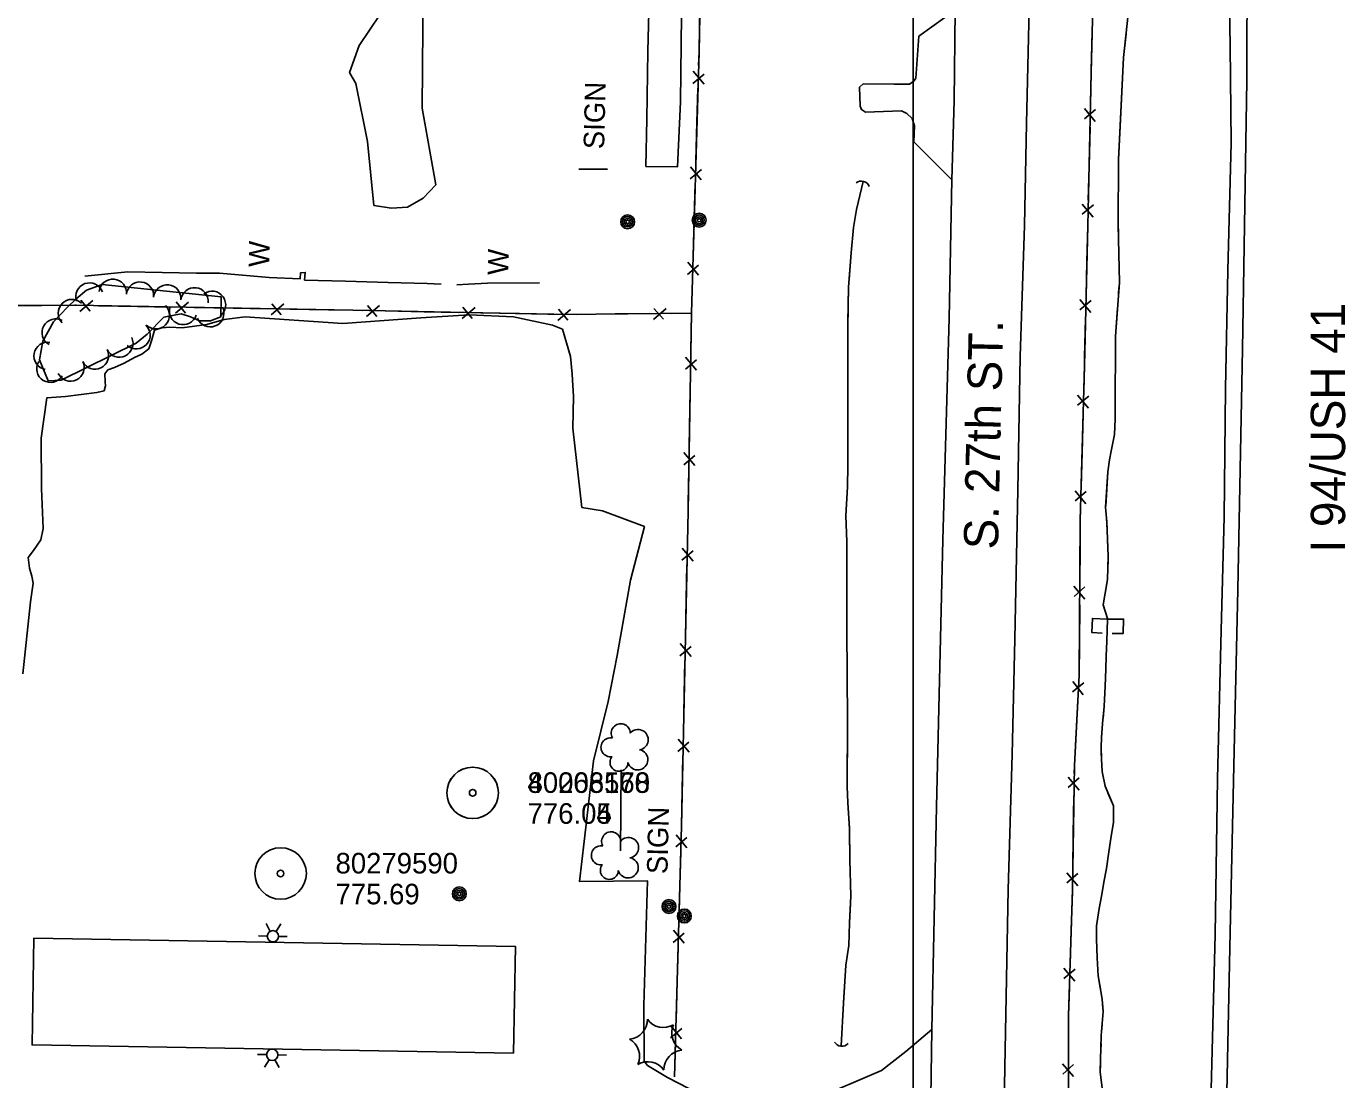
# Model space of a CAD drawing. Extents: x 591954 to 597000, y 198576 to 213500.
# Drawn here: x 593741.5 to 594126.1, y 209562.4 to 209869.5 of the extents above; entities that cross this region are included whole.
import ezdxf

# ---------------------------------------------------------------- set-up
doc = ezdxf.new("R2010")
doc.units = 0
for name, color, linetype in [('1', 7, 'Continuous'), ('Level 10', 7, 'Continuous'), ('Level 11', 7, 'Continuous'), ('Level 12', 7, 'Continuous'), ('Level 14', 7, 'Continuous'), ('Level 15', 7, 'Continuous'), ('Level 17', 7, 'Continuous'), ('Level 18', 7, 'Continuous'), ('Level 19', 7, 'Continuous'), ('Level 6', 7, 'Continuous')]:
    doc.layers.add(name, color=color, linetype=linetype)

msp = doc.modelspace()

# ---------------------------------------------------------------- linework, layer by layer
at = {"layer": 'Level 10'}
for p, q in [((594000, 209500), (594000, 210500)), ((594000, 208500), (594000, 210000))]:
    msp.add_line(p, q, dxfattribs=at)
at = {"layer": 'Level 11'}
for points in [[(594091.31, 209554.07), (594092.34, 209600.93), (594093.45, 209653.95), (594094.63, 209705.34), (594096.03, 209775.4), (594097.26, 209853.63), (594097.48, 209924.76), (594097.61, 209991.03), (594097.47, 210057.15), (594095.7, 210107.83), (594092.7, 210159.9), (594089.31, 210197.02), (594083.96, 210243.66), (594078.7, 210282.56), (594060.94, 210385.67)], [(594086.72, 209555.89), (594087.98, 209604.77), (594088.71, 209650.16), (594089.73, 209693.47), (594090.69, 209726.46), (594091.06, 209763.95), (594091.76, 209798.33), (594092.66, 209835.57), (594092.35, 209863.88), (594091.82, 209896.8)], [(594034.04, 209883.08), (594033, 209841.22), (594032.48, 209811.52), (594031.17, 209773.23), (594030.5, 209734.28), (594029.58, 209690.89), (594028.84, 209657.2), (594027.72, 209617.9), (594026.37, 209550.34)], [(594011.28, 209824.83), (594011.94, 209847.85), (594012.22, 209874.26)], [(594005.47, 209577.06), (594006.8, 209641.94), (594008.65, 209719.87), (594010.5, 209784.41), (594011.28, 209824.83)], [(594005.08, 209550.72), (594005.47, 209577.06)]]:
    msp.add_lwpolyline(points, dxfattribs=at)
at = {"layer": 'Level 12'}
msp.add_lwpolyline([(593883.47, 209570.18), (593743.1, 209572.58), (593743.64, 209603.71), (593884.01, 209601.3), (593883.47, 209570.18)], dxfattribs=at)
at = {"layer": 'Level 14'}
for p, q in [((593812.54, 209605.67), (593811.34, 209607.97)), ((593814.24, 209605.66), (593815.61, 209607.89)), ((593811.7, 209604.3), (593809.1, 209604.37)), ((593814.98, 209604.21), (593817.5, 209604.14)), ((593812.46, 209602.81), (593812.29, 209602.53)), ((593814.1, 209602.77), (593814.25, 209602.5)), ((593811.48, 209569.73), (593808.88, 209569.8)), ((593812.32, 209571.1), (593812.16, 209571.4)), ((593814.02, 209571.09), (593814.19, 209571.37)), ((593814.76, 209569.64), (593817.28, 209569.57)), ((593812.24, 209568.24), (593810.88, 209566.05)), ((593813.88, 209568.2), (593815.12, 209566.02))]:
    msp.add_line(p, q, dxfattribs=at)
for points in [[(593910.85, 209827.88), (593902.52, 209827.87)], [(593914.65, 209629.17), (593914.81, 209652.75)]]:
    msp.add_lwpolyline(points, dxfattribs=at)
for centre, radius in [((593937.58, 209813.02), 2.02), ((593916.74, 209812.56), 2.02), ((593916.74, 209812.58), 1.52), ((593916.75, 209812.54), 1.01), ((593916.75, 209812.55), 0.502), ((593937.58, 209813.03), 1.52), ((593937.58, 209812.99), 1.01), ((593937.59, 209813), 0.502), ((593867.67, 209616.61), 2.02), ((593867.67, 209616.62), 1.52), ((593867.68, 209616.58), 1.01), ((593867.68, 209616.59), 0.502), ((593928.8, 209612.91), 2.02), ((593928.79, 209612.92), 1.52), ((593928.8, 209612.88), 1.01), ((593928.8, 209612.89), 0.502), ((593933.27, 209610.14), 2.02), ((593933.27, 209610.15), 1.52), ((593933.28, 209610.11), 1.01), ((593933.28, 209610.12), 0.502), ((593813.34, 209604.24), 1.64), ((593813.12, 209569.67), 1.64)]:
    msp.add_circle(centre, radius, dxfattribs=at)
at = {"layer": 'Level 15'}
for p, q in [((593935.79, 209852.91), (593939.04, 209855.61)), ((593939.02, 209852.65), (593935.89, 209856.46)), ((594049.92, 209845.56), (594053.07, 209841.77)), ((594053.16, 209845.32), (594049.92, 209842.6)), ((593934.98, 209825.06), (593938.23, 209827.77)), ((593938.21, 209824.8), (593935.08, 209828.61)), ((594049.27, 209817.71), (594052.43, 209813.92)), ((594052.51, 209817.47), (594049.27, 209814.74)), ((593934.17, 209797.21), (593937.42, 209799.92)), ((593937.4, 209796.95), (593934.27, 209800.76)), ((593757.07, 209786.44), (593760.85, 209789.61)), ((593757.3, 209789.67), (593760.04, 209786.45)), ((593784.93, 209785.94), (593788.7, 209789.11)), ((593785.16, 209789.18), (593787.89, 209785.96)), ((593812.78, 209785.44), (593816.56, 209788.61)), ((593813.01, 209788.68), (593815.75, 209785.46)), ((593840.64, 209784.94), (593844.42, 209788.1)), ((593840.87, 209788.17), (593843.6, 209784.95)), ((594048.62, 209789.86), (594051.77, 209786.07)), ((594051.86, 209789.61), (594048.62, 209786.89)), ((593868.49, 209784.38), (593872.27, 209787.55)), ((593868.72, 209787.62), (593871.46, 209784.39)), ((593896.37, 209783.8), (593900.1, 209787.02)), ((593896.56, 209787.05), (593899.33, 209783.85)), ((593924.25, 209784.04), (593927.94, 209787.32)), ((593924.39, 209787.28), (593927.22, 209784.14)), ((593936.8, 209769.34), (593933.63, 209773.11)), ((593933.57, 209769.57), (593936.78, 209772.31)), ((594051.18, 209761.76), (594047.93, 209759.05)), ((594047.94, 209762.01), (594051.08, 209758.21)), ((593933.1, 209741.71), (593936.32, 209744.45)), ((593936.33, 209741.49), (593933.16, 209745.26)), ((594050.43, 209733.91), (594047.19, 209731.2)), ((594047.2, 209734.16), (594050.34, 209730.36)), ((593932.57, 209713.86), (593935.8, 209716.59)), ((593935.81, 209713.63), (593932.65, 209717.41)), ((594046.84, 209706.27), (594050.05, 209702.53)), ((594050.07, 209706.08), (594046.88, 209703.31)), ((593931.99, 209686.01), (593935.22, 209688.74)), ((593935.22, 209685.77), (593932.06, 209689.56)), ((594049.78, 209678.15), (594046.46, 209675.53)), ((594046.56, 209678.5), (594049.59, 209674.61)), ((593934.64, 209657.92), (593931.48, 209661.7)), ((593931.4, 209658.16), (593934.63, 209660.88)), ((594045.18, 209650.61), (594048.36, 209646.84)), ((594048.42, 209650.39), (594045.2, 209647.64)), ((593930.78, 209630.31), (593934.03, 209633.02)), ((593934.02, 209630.05), (593930.88, 209633.86)), ((594044.76, 209622.75), (594047.95, 209618.98)), ((594048, 209622.53), (594044.79, 209619.78)), ((593930.02, 209602.46), (593933.27, 209605.17)), ((593933.26, 209602.2), (593930.12, 209606.01)), ((594047.18, 209594.66), (594043.92, 209591.96)), ((594043.95, 209594.93), (594047.07, 209591.11)), ((593929.26, 209574.61), (593932.51, 209577.32)), ((593932.49, 209574.36), (593929.36, 209578.16)), ((594043.52, 209567.02), (594046.77, 209563.31)), ((594046.76, 209566.85), (594043.59, 209564.06))]:
    msp.add_line(p, q, dxfattribs=at)
for points in [[(593959.51, 210454.78), (593974.64, 210411.96), (593987.13, 210374.2), (593999.11, 210340.41), (594023.86, 210270.06), (594042.85, 210215.9), (594047.69, 210154.51), (594052.6, 210098.45), (594056.62, 210050.32), (594056.88, 210021.22), (594055.97, 209983.92), (594054.43, 209941.9), (594052.89, 209894.6), (594051.91, 209856.12), (594050.87, 209811.42), (594049.91, 209770.63), (594048.71, 209725.59), (594048.4, 209680.32), (594046.97, 209654.07), (594046.43, 209617.89), (594045.25, 209581.13), (594045.27, 209558.54), (594045.21, 209556.37)], [(593935.34, 209785.89), (593937.56, 209862.11), (593939.67, 209972.11), (593940.13, 210009.6)], [(593937.7, 209869.43), (593937.89, 209879.39)], [(593937.44, 209858.12), (593937.56, 209862.11), (593937.7, 209869.43)], [(594052.21, 209867.96), (594051.92, 209856.64)], [(594051.92, 209856.64), (594051.91, 209856.12), (594051.69, 209846.68)], [(593936.96, 209841.58), (593937.25, 209851.54)], [(593936.63, 209830.27), (593936.96, 209841.58)], [(594051.54, 209840.1), (594051.27, 209828.79)], [(594051.27, 209828.79), (594051.04, 209818.83)], [(593936.15, 209813.74), (593936.44, 209823.69)], [(593935.82, 209802.42), (593936.15, 209813.74)], [(594050.89, 209812.25), (594050.87, 209811.42), (594050.62, 209800.93)], [(594050.62, 209800.93), (594050.39, 209790.98)], [(593862.41, 209794.4), (593858.34, 209794.58), (593846.96, 209794.84), (593834.51, 209795.28), (593822.57, 209795.56), (593822.77, 209797.77), (593821.41, 209797.72), (593821.24, 209795.92), (593812.2, 209796.34), (593797.74, 209797.62), (593791.02, 209797.57), (593771.07, 209797.98), (593758.49, 209796.74)], [(593935.34, 209785.89), (593935.63, 209795.84)], [(593891.07, 209794.77), (593875.86, 209794.68), (593870.36, 209794.39), (593866.92, 209794.22)], [(593677.4, 209540.09), (593681.55, 209631.44), (593686.02, 209748.26), (593687.78, 209788.12), (593755.63, 209788.2), (593836.66, 209786.76), (593898.23, 209785.53), (593935.34, 209785.89)], [(593734.67, 209788.18), (593745.99, 209788.19)], [(593745.99, 209788.19), (593755.63, 209788.2), (593755.94, 209788.2)], [(593762.52, 209788.08), (593773.84, 209787.88)], [(593773.84, 209787.88), (593783.8, 209787.7)], [(593790.38, 209787.58), (593801.7, 209787.38)], [(593801.7, 209787.38), (593811.65, 209787.2)], [(593818.23, 209787.08), (593829.56, 209786.88)], [(593829.56, 209786.88), (593836.66, 209786.76), (593839.51, 209786.7)], [(593846.09, 209786.57), (593857.41, 209786.34)], [(593857.41, 209786.34), (593867.36, 209786.14)], [(593873.95, 209786.01), (593885.26, 209785.79)], [(593885.26, 209785.79), (593895.22, 209785.59)], [(593901.8, 209785.56), (593913.12, 209785.67)], [(593913.12, 209785.67), (593923.08, 209785.77)], [(593929.66, 209785.83), (593935.34, 209785.89)], [(593930.45, 209563.29), (593932.45, 209636.37), (593934.37, 209728.16), (593935.34, 209785.89)], [(593935.16, 209774.79), (593935.34, 209785.89)], [(594050.23, 209784.4), (594049.97, 209773.08)], [(594049.97, 209773.08), (594049.91, 209770.63), (594049.71, 209763.13)], [(593934.88, 209758.26), (593935.04, 209768.21)], [(593934.69, 209746.94), (593934.88, 209758.26)], [(594049.54, 209756.55), (594049.23, 209745.23)], [(594049.23, 209745.23), (594048.97, 209735.28)], [(593934.41, 209730.4), (593934.58, 209740.36)], [(593934.18, 209719.08), (593934.37, 209728.16), (593934.41, 209730.4)], [(594048.79, 209728.7), (594048.71, 209725.59), (594048.65, 209717.38)], [(594048.65, 209717.38), (594048.58, 209707.42)], [(593933.83, 209702.55), (593934.04, 209712.5)], [(593933.6, 209691.23), (593933.83, 209702.55)], [(594048.54, 209700.84), (594048.46, 209689.52)], [(594058.03, 209692.48), (594061.22, 209692.56), (594061.35, 209696.74), (594056.66, 209696.73), (594052.26, 209696.91), (594052.06, 209692.84), (594055.06, 209692.61)], [(594048.46, 209689.52), (594048.4, 209680.32), (594048.35, 209679.56)], [(593933.25, 209674.69), (593933.46, 209684.65)], [(593933.01, 209663.38), (593933.25, 209674.69)], [(594048, 209672.99), (594047.39, 209661.69)], [(594047.39, 209661.69), (594046.97, 209654.07), (594046.94, 209651.74)], [(593932.67, 209646.84), (593932.88, 209656.79)], [(593932.43, 209635.52), (593932.45, 209636.37), (593932.67, 209646.84)], [(594046.84, 209645.16), (594046.67, 209633.84)], [(594046.67, 209633.84), (594046.52, 209623.88)], [(593931.97, 209618.99), (593932.24, 209628.94)], [(593931.67, 209607.67), (593931.97, 209618.99)], [(594046.41, 209617.3), (594046.05, 209605.99)], [(594046.05, 209605.99), (594045.73, 209596.04)], [(593931.21, 209591.14), (593931.48, 209601.09)], [(593930.9, 209579.82), (593931.21, 209591.14)], [(594045.52, 209589.46), (594045.25, 209581.13), (594045.25, 209578.14)], [(594045.25, 209578.14), (594045.26, 209568.18)], [(593930.45, 209563.29), (593930.72, 209573.24)]]:
    msp.add_lwpolyline(points, dxfattribs=at)
for centre, start, end in [((593984.89, 209821.91), 22.3381, 128.5777), ((593979.19, 209574.67), 210.7721, 317.0116)]:
    msp.add_arc(centre, 2.5, start, end, dxfattribs=at)
at = {"layer": 'Level 17'}
for points in [[(593817.2, 209957.57), (593831.95, 209961.46), (593837.63, 209961.64), (593840.77, 209960.49), (593842.74, 209958.25), (593844.01, 209947.49), (593844.5, 209878.07), (593844.47, 209872.94), (593838.47, 209863.97), (593835.68, 209856.08), (593837.51, 209852.91), (593840.95, 209835.99), (593842.79, 209817.33), (593847.87, 209816.55), (593852.52, 209816.86), (593857.15, 209819.42), (593860.79, 209823.33), (593856.81, 209845.73), (593857.38, 209916.41), (593857.82, 209957.12), (593859.55, 209969.52), (593862.11, 209978.24), (593875.52, 209996.25)], [(593932.42, 209970.11), (593933.31, 209953.24), (593932.36, 209914.25), (593932.52, 209881.21), (593932.11, 209847.5), (593931.28, 209828.54), (593922.06, 209828.72), (593922.34, 209842.48), (593922.66, 209862.28), (593922.9, 209873.68), (593923.6, 209898.68), (593924.46, 209916.94), (593924.74, 209923.21), (593924.41, 209943.26), (593923.77, 209956.53), (593923.75, 209970.8)], [(594010.25, 209872.85), (594009.25, 209872.13), (594001.59, 209866.64), (594000.74, 209854.47), (594000.13, 209853.6), (593998.87, 209852.7), (593997.7, 209852.64), (593994.43, 209852.71), (593985.38, 209852.74), (593984.31, 209851.8), (593984.53, 209846.26), (593984.95, 209845.25), (593986.06, 209844.51), (593996.59, 209844.89), (593998.16, 209844.17), (593999.68, 209842.66), (594000.35, 209840.49), (594000.2, 209835.82), (594011.28, 209824.83)], [(593921.55, 209567.84), (593921.46, 209584.03), (593922.49, 209620.43), (593902.67, 209620.21), (593904.06, 209631.85), (593906.79, 209655.41), (593911.04, 209672.65), (593913.65, 209686.12), (593917.57, 209708.11), (593921.62, 209723.71), (593909.4, 209728.29), (593903.38, 209729.26), (593900.81, 209752.42), (593900.92, 209761.62), (593900.55, 209768.13), (593900.12, 209773.24), (593897.72, 209781.2), (593894.87, 209782.37), (593883.45, 209784.89), (593870.59, 209785.43), (593856.45, 209784.6), (593833.71, 209782.89), (593805.2, 209784.82), (593799.12, 209784.05), (593794.1, 209782.64), (593786.87, 209781.68), (593783.32, 209781.79), (593780.94, 209781.68), (593778.79, 209780.96), (593777.91, 209777.84), (593777.14, 209775.52), (593775.07, 209773.97), (593772.97, 209772.98), (593769.97, 209771.34), (593767.18, 209770.08), (593765.25, 209769.43), (593764.33, 209768.22), (593764.4, 209765.89), (593764.5, 209764.73), (593764.11, 209763.31), (593761.98, 209762.83), (593752.85, 209761.64), (593747.41, 209761.19), (593745.74, 209749.49), (593745.89, 209734.8), (593746.32, 209723.1), (593745.69, 209719.81), (593743.51, 209716.67), (593742.02, 209714.63), (593742.41, 209711.53), (593743.08, 209709.23), (593743.41, 209707.19), (593742.65, 209701.79), (593740.45, 209680.73)], [(594005.47, 209577.06), (593997.81, 209570.62), (593990.8, 209565.1), (593971.23, 209556.73), (593957.64, 209556.9), (593940.71, 209557.81), (593934.54, 209559.89), (593928.32, 209563.04), (593922.55, 209566.54), (593921.55, 209567.84)]]:
    msp.add_lwpolyline(points, dxfattribs=at)
at = {"layer": 'Level 18'}
msp.add_lwpolyline([(593773.43, 209777.14), (593776.69, 209779.8), (593781.58, 209784.71), (593786.58, 209785.7), (593789.33, 209784.81), (593791.9, 209783.72), (593795.17, 209783.69), (593798.19, 209784.86), (593798.28, 209790.66), (593763.57, 209794.29), (593758.98, 209792.66), (593755.94, 209790.09), (593753.44, 209787.63), (593749.35, 209783.42), (593746.27, 209777.76), (593745.32, 209772.3), (593747.86, 209766.18), (593751.58, 209766.36), (593773.43, 209777.14)], dxfattribs=at)
for centre, radius, start, end in [((593914.75, 209663.42), 2.78, 1.3946, 209.1675), ((593911.75, 209659.34), 2.78, 78.0716, 279.0826), ((593919.79, 209661.56), 2.97, 278.4237, 139.6575), ((593919.68, 209655.7), 2.97, 196.0745, 79.0477), ((593914.21, 209654.94), 2.61, 140.7797, 358.7123), ((593911.94, 209631.92), 2.78, 1.3946, 209.1675), ((593908.94, 209627.84), 2.78, 78.0716, 279.0826), ((593916.98, 209630.06), 2.97, 278.4237, 139.6575), ((593916.87, 209624.21), 2.97, 196.0745, 79.0477), ((593911.4, 209623.44), 2.61, 140.7797, 358.7123), ((593916.78, 209579.96), 5.72, 275.2113, 0.9762), ((593927.18, 209583.36), 5.72, 215.2113, 300.9762), ((593935.32, 209576.05), 5.72, 155.2113, 240.9762), ((593914.52, 209569.26), 5.72, 335.2113, 60.9762), ((593933.06, 209565.35), 5.72, 95.2113, 180.9762), ((593922.66, 209561.95), 5.72, 35.2113, 120.9762)]:
    msp.add_arc(centre, radius, start, end, dxfattribs=at)
for centre, major_axis, ratio, start_param, end_param in [((593766.64, 209791.86), (2.86, 2.79), 0.996475, 5.40392, 8.545245), ((593759.85, 209790.76), (2.97, 2.67), 0.995849, 5.889612, 9.030937), ((593774.58, 209791.03), (2.86, 2.79), 0.996475, 5.40392, 8.545245), ((593782.52, 209790.2), (2.86, 2.79), 0.996475, 5.40392, 8.545245), ((593790.46, 209789.37), (2.86, 2.79), 0.996475, 5.40392, 8.545245), ((593795.58, 209788.34), (1.14, -3.83), 0.99657, 0.340366, 3.481692), ((593754.71, 209785.95), (2.04, 3.44), 0.994862, 6.045583, 9.186908), ((593779.22, 209785.29), (-2.74, -2.91), 0.995155, 6.253959, 9.395284), ((593750.01, 209780.27), (1.97, 3.48), 0.995255, 0.016088, 3.157413), ((593787.15, 209786.55), (-3.5, 1.94), 0.999352, 0.193403, 3.334729), ((593795.06, 209785.89), (-3.95, -0.63), 0.99614, 0.212479, 3.353804), ((593773.58, 209779.48), (-2.19, -3.35), 0.994996, 6.124495, 9.26582), ((593747.64, 209773.46), (0.19, 4), 0.996182, 6.158984, 9.30031), ((593768.59, 209777.08), (-0.97, -3.88), 0.990291, 5.410305, 8.551631), ((593761.46, 209773.56), (-0.97, -3.88), 0.990291, 5.410305, 8.551631), ((593748.48, 209769.7), (-1.84, 3.55), 0.99846, 0.54232, 3.683645), ((593754.33, 209770.04), (-0.97, -3.88), 0.990291, 5.410305, 8.551631)]:
    msp.add_ellipse(centre, major_axis=major_axis, ratio=ratio, start_param=start_param, end_param=end_param, dxfattribs=at)
at = {"layer": 'Level 19'}
for points in [[(594062.62, 209873.13), (594061.33, 209860.42), (594059.87, 209830.74), (594059.79, 209811.69), (594060.1, 209794.87), (594058.98, 209779.25), (594058.97, 209770.73), (594058.88, 209765.66), (594058.89, 209760.56), (594058.85, 209755.01), (594058.7, 209750.54), (594057.7, 209745.67), (594057.21, 209743.19), (594056.75, 209739.65), (594056.1, 209729.37), (594056.43, 209725.07), (594056.85, 209715.08), (594056.61, 209708.28), (594055.39, 209700.85), (594056.61, 209696.86)], [(594060.24, 209838.38), (594061.33, 209860.42), (594062.04, 209867.32)], [(594059.83, 209809.39), (594059.79, 209811.69), (594059.87, 209830.74), (594060.24, 209838.38)], [(593985.42, 209824.32), (593983.46, 209816.13), (593982.55, 209810.89), (593981.9, 209803.55), (593981.18, 209793.51), (593980.93, 209783.23), (593980.92, 209741.37), (593980.82, 209735.25), (593980.34, 209726.83), (593980.66, 209719.3), (593980.64, 209710.06), (593980.66, 209700.66), (593980.67, 209693.76), (593980.79, 209680.6), (593980.87, 209667.05), (593980.75, 209647.91), (593980.94, 209643.11), (593981.42, 209635.55), (593981.51, 209626.53), (593981.77, 209616.07), (593981.45, 209608.19), (593981.24, 209601.55), (593980.37, 209595.84), (593979.7, 209584.72), (593979, 209572.25)], [(593985.42, 209824.32), (593983.46, 209816.13), (593982.55, 209810.89), (593981.9, 209803.55), (593981.33, 209795.68)], [(594059.94, 209803.39), (594059.91, 209805.39)], [(594060.05, 209797.39), (594060.01, 209799.39)], [(594059.85, 209791.4), (594059.99, 209793.4)], [(593981.13, 209791.69), (593981.08, 209789.69)], [(593980.99, 209785.69), (593980.94, 209783.69)], [(594058.87, 209758.43), (594058.89, 209760.56), (594058.88, 209765.66), (594058.97, 209770.73), (594058.98, 209779.25), (594059.56, 209787.41)], [(593980.93, 209779.69), (593980.93, 209777.69)], [(593980.93, 209773.69), (593980.92, 209744.69)], [(594056.11, 209729.64), (594056.75, 209739.65), (594057.21, 209743.19), (594057.7, 209745.67), (594058.7, 209750.54), (594058.85, 209755.01), (594058.87, 209758.43)], [(593980.92, 209744.69), (593980.92, 209741.37), (593980.82, 209735.25), (593980.34, 209726.83), (593980.66, 209719.3), (593980.65, 209715.72)], [(594056.49, 209723.65), (594056.43, 209725.07), (594056.38, 209725.65)], [(594056.74, 209717.65), (594056.66, 209719.65)], [(593980.65, 209711.72), (593980.64, 209710.06), (593980.64, 209709.72)], [(594056.73, 209711.66), (594056.8, 209713.66)], [(594056.61, 209696.86), (594055.39, 209700.85), (594056.51, 209707.67)], [(593980.65, 209705.72), (593980.65, 209703.72)], [(593980.66, 209699.72), (593980.66, 209697.72)], [(594056.61, 209696.73), (594056.48, 209690.26), (594056.24, 209685.91), (594056.12, 209682.14), (594055.97, 209677.19), (594055.65, 209671.26), (594055.19, 209666.32), (594054.91, 209662.09), (594054.77, 209659.48), (594054.85, 209655.9), (594055.06, 209652.24), (594055.93, 209648.01), (594058.43, 209642.27), (594058.36, 209637.45), (594057.68, 209633.38), (594056.9, 209628.15), (594056.32, 209623.97), (594055.54, 209619.99), (594055.02, 209616.39), (594054.21, 209612.37), (594053.4, 209607.24), (594053.43, 209603.51), (594053.67, 209597.97), (594053.92, 209592.7), (594055.08, 209585.87), (594055.34, 209582.28), (594054.83, 209575.27), (594054.47, 209564.7), (594055.73, 209554.45)], [(594055.33, 209667.76), (594055.65, 209671.26), (594055.97, 209677.19), (594056.12, 209682.14), (594056.24, 209685.91), (594056.48, 209690.26), (594056.61, 209696.73)], [(594056.61, 209696.86), (594056.61, 209696.73)], [(594056.61, 209696.86), (594056.61, 209696.73)], [(593980.67, 209693.72), (593980.79, 209680.6), (593980.87, 209667.05), (593980.86, 209664.72)], [(593980.86, 209664.72), (593980.75, 209647.91), (593980.94, 209643.11), (593981.41, 209635.74)], [(594054.9, 209661.78), (594054.91, 209662.09), (594055.02, 209663.77)], [(594054.86, 209655.78), (594054.85, 209655.9), (594054.81, 209657.78)], [(594055.55, 209649.84), (594055.15, 209651.8)], [(594055.2, 209617.65), (594055.54, 209619.99), (594056.32, 209623.97), (594056.9, 209628.15), (594057.68, 209633.38), (594058.36, 209637.45), (594058.43, 209642.27), (594056.78, 209646.05)], [(593981.46, 209631.74), (593981.48, 209629.74)], [(593981.53, 209625.74), (593981.58, 209623.75)], [(593981.68, 209619.75), (593981.73, 209617.75)], [(594054.57, 209588.87), (594053.92, 209592.7), (594053.67, 209597.97), (594053.43, 209603.51), (594053.4, 209607.24), (594054.21, 209612.37), (594055.02, 209616.39), (594055.2, 209617.65)], [(593981.67, 209613.75), (593981.45, 209608.19), (593981.24, 209601.55), (593980.37, 209595.84), (593979.71, 209584.85)], [(593979.71, 209584.85), (593979.7, 209584.72), (593979, 209572.25)], [(594055.29, 209582.93), (594055.15, 209584.92)], [(594054.95, 209576.94), (594055.1, 209578.93)], [(594054.68, 209570.95), (594054.75, 209572.95)], [(594054.46, 209550.86), (594055.52, 209552.53), (594055.73, 209554.45), (594054.47, 209564.7), (594054.55, 209566.95)]]:
    msp.add_lwpolyline(points, dxfattribs=at)
at = {"layer": 'Level 6'}
for centre, radius in [((593871.56, 209646.04), 7.5), ((593871.56, 209646.04), 7.5), ((593871.57, 209646.04), 7.5), ((593871.57, 209646.04), 7.5), ((593871.56, 209646.04), 0.96), ((593871.56, 209646.04), 0.96), ((593871.57, 209646.04), 0.96), ((593871.57, 209646.04), 0.96), ((593815.58, 209622.55), 7.5), ((593815.58, 209622.55), 7.5), ((593815.58, 209622.55), 0.96), ((593815.58, 209622.55), 0.96)]:
    msp.add_circle(centre, radius, dxfattribs=at)

# ---------------------------------------------------------------- texts
at = {"layer": '1'}
for s, rotation, p in [('I 94/USH 41', 90, (594125.91, 209716.11)), ('S. 27th ST.', 88.7128, (594024.71, 209716.96))]:
    msp.add_text(s, height=10, rotation=rotation, dxfattribs=at).set_placement(p)
at = {"layer": 'Level 14'}
for p in [(593909.89, 209833.67), (593928.35, 209622.31)]:
    msp.add_text('SIGN', height=6, rotation=88.6883, dxfattribs=at).set_placement(p)
at = {"layer": 'Level 15'}
for p in [(593812.26, 209799.35), (593881.96, 209797.02)]:
    msp.add_text('W', height=6, rotation=89.144, dxfattribs=at).set_placement(p)
at = {"layer": 'Level 6'}
for s, p in [('40066560', (593887.56, 209646.04)), ('40066560', (593887.56, 209646.04)), ('80208178', (593887.57, 209646.04)), ('80208178', (593887.57, 209646.04)), ('776.04', (593887.56, 209637.04)), ('776.04', (593887.56, 209637.04)), ('776.05', (593887.57, 209637.04)), ('776.05', (593887.57, 209637.04)), ('80279590', (593831.58, 209622.55)), ('80279590', (593831.58, 209622.55)), ('775.69', (593831.58, 209613.55)), ('775.69', (593831.58, 209613.55))]:
    msp.add_text(s, height=6, dxfattribs=at).set_placement(p)

doc.saveas('drawing.dxf')
